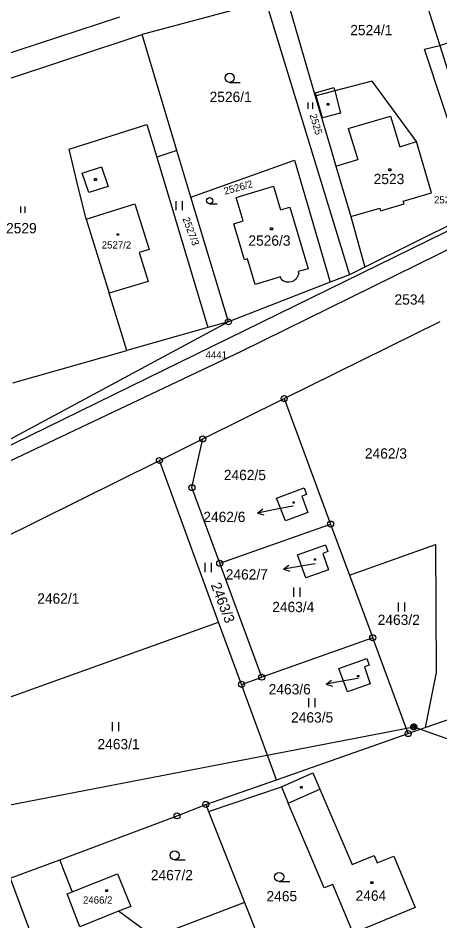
# Model space of a CAD drawing. Extents: x -468021 to -466942, y -1130484 to -1128584.
# Drawn here: x -467879.7 to -467810, y -1129830.2 to -1129681.1 of the extents above; entities that cross this region are included whole.
import ezdxf

# ---------------------------------------------------------------- set-up
doc = ezdxf.new("R2010")
doc.units = 0
doc.layers.add('DKM', color=7, linetype='Continuous')

msp = doc.modelspace()

# ---------------------------------------------------------------- linework, layer by layer
at = {"layer": 'DKM'}
for p, q in [((-467814.36, -1129671.87), (-467810.02, -1129685.66)), ((-467835.37, -1129677.48), (-467830.6, -1129694.02)), ((-467838.73, -1129678.38), (-467859.18, -1129683.85)), ((-467838.73, -1129678.38), (-467824.94, -1129723.51)), ((-467862.9, -1129680.96), (-467888.61, -1129689.4)), ((-467894.35, -1129695.47), (-467859.18, -1129683.85)), ((-467857.14, -1129690.66), (-467859.18, -1129683.85)), ((-467812.52, -1129686.25), (-467810.02, -1129685.66)), ((-467810.02, -1129685.66), (-467805.91, -1129684.3)), ((-467810.02, -1129685.66), (-467801.73, -1129712)), ((-467803.72, -1129712.98), (-467812.52, -1129686.25)), ((-467853.43, -1129703.02), (-467857.14, -1129690.66)), ((-467821.18, -1129691.55), (-467827.34, -1129693.17)), ((-467813.83, -1129701.51), (-467821.18, -1129691.55)), ((-467844.73, -1129691.74), (-467842.98, -1129691.74)), ((-467830.56, -1129693.49), (-467827.49, -1129692.6)), ((-467827.49, -1129692.6), (-467827.34, -1129693.17)), ((-467830.42, -1129693.97), (-467830.6, -1129694.02)), ((-467830.6, -1129694.02), (-467828.01, -1129702.73)), ((-467830.42, -1129693.97), (-467830.56, -1129693.49)), ((-467827.34, -1129693.17), (-467830.42, -1129693.97)), ((-467829.36, -1129697.62), (-467830.42, -1129693.97)), ((-467827.34, -1129693.17), (-467826.39, -1129696.83)), ((-467831.75, -1129696.11), (-467831.75, -1129695.06)), ((-467831.05, -1129695.06), (-467831.05, -1129696.11)), ((-467828.61, -1129695.23), (-467828.31, -1129695.23)), ((-467828.61, -1129695.53), (-467828.61, -1129695.23)), ((-467828.31, -1129695.53), (-467828.61, -1129695.53)), ((-467828.31, -1129695.23), (-467828.31, -1129695.53)), ((-467826.39, -1129696.83), (-467829.36, -1129697.62)), ((-467825.13, -1129699.37), (-467818.16, -1129697.35)), ((-467818.16, -1129697.35), (-467816.62, -1129702.37)), ((-467871.25, -1129702.79), (-467858.38, -1129698.7)), ((-467858.38, -1129698.7), (-467856.76, -1129704.09)), ((-467825.13, -1129699.37), (-467823.54, -1129704.48)), ((-467816.62, -1129702.37), (-467813.83, -1129701.51)), ((-467811.35, -1129709.98), (-467813.83, -1129701.51)), ((-467896.28, -1129759.16), (-467780.41, -1129702.4)), ((-467869.89, -1129708.32), (-467871.25, -1129702.79)), ((-467853.43, -1129703.02), (-467856.76, -1129704.09)), ((-467851.12, -1129710.71), (-467853.43, -1129703.02)), ((-467842.76, -1129736.13), (-467776.17, -1129703.37)), ((-467828.01, -1129702.73), (-467827.16, -1129705.59)), ((-467856.76, -1129704.09), (-467848.31, -1129732.25)), ((-467851.12, -1129710.71), (-467834.03, -1129704.6)), ((-467834.03, -1129704.6), (-467828.09, -1129724.74)), ((-467827.16, -1129705.59), (-467823.54, -1129704.48)), ((-467869.09, -1129706.76), (-467865.87, -1129705.7)), ((-467865.87, -1129705.7), (-467864.81, -1129708.92)), ((-467827.16, -1129705.59), (-467824.68, -1129713.91)), ((-467818.41, -1129706.03), (-467818.11, -1129706.03)), ((-467818.41, -1129706.33), (-467818.41, -1129706.03)), ((-467818.11, -1129706.33), (-467818.41, -1129706.33)), ((-467818.11, -1129706.03), (-467818.11, -1129706.33)), ((-467867.99, -1129709.95), (-467869.09, -1129706.76)), ((-467867.03, -1129707.64), (-467866.73, -1129707.64)), ((-467867.03, -1129707.94), (-467867.03, -1129707.64)), ((-467866.73, -1129707.94), (-467867.03, -1129707.94)), ((-467866.73, -1129707.64), (-467866.73, -1129707.94)), ((-467868.42, -1129714.33), (-467869.89, -1129708.32)), ((-467864.81, -1129708.92), (-467867.99, -1129709.95)), ((-467843.66, -1129710.75), (-467837.47, -1129708.91)), ((-467837.47, -1129708.91), (-467836.32, -1129712.79)), ((-467844.92, -1129731.29), (-467851.12, -1129710.71)), ((-467842.51, -1129714.62), (-467843.66, -1129710.75)), ((-467816.03, -1129711.36), (-467811.35, -1129709.98)), ((-467879.24, -1129713.31), (-467879.24, -1129712.26)), ((-467878.54, -1129712.26), (-467878.54, -1129713.31)), ((-467868.42, -1129714.33), (-467860.37, -1129711.79)), ((-467860.37, -1129711.79), (-467858.03, -1129719.32)), ((-467853.56, -1129712.87), (-467853.56, -1129711.37)), ((-467852.56, -1129711.37), (-467852.56, -1129712.87)), ((-467848.03, -1129711.81), (-467846.8, -1129711.81)), ((-467836.32, -1129712.79), (-467834.78, -1129712.33)), ((-467834.78, -1129712.33), (-467831.74, -1129722.51)), ((-467819.8, -1129712.94), (-467815.9, -1129711.79)), ((-467815.9, -1129711.79), (-467816.03, -1129711.36)), ((-467824.68, -1129713.91), (-467819.93, -1129712.51)), ((-467824.68, -1129713.91), (-467822.41, -1129722.26)), ((-467803.72, -1129712.98), (-467822.41, -1129722.26)), ((-467819.93, -1129712.51), (-467819.8, -1129712.94)), ((-467868.42, -1129714.33), (-467864.61, -1129726.57)), ((-467844.05, -1129715.08), (-467842.51, -1129714.62)), ((-467842.28, -1129721.05), (-467844.05, -1129715.08)), ((-467863.3, -1129716.75), (-467863.09, -1129716.75)), ((-467863.3, -1129716.96), (-467863.3, -1129716.75)), ((-467863.09, -1129716.96), (-467863.3, -1129716.96)), ((-467863.09, -1129716.75), (-467863.09, -1129716.96)), ((-467837.96, -1129715.78), (-467837.66, -1129715.78)), ((-467837.96, -1129716.08), (-467837.96, -1129715.78)), ((-467837.66, -1129716.08), (-467837.96, -1129716.08)), ((-467837.66, -1129715.78), (-467837.66, -1129716.08)), ((-467858.03, -1129719.32), (-467859.64, -1129719.82)), ((-467859.64, -1129719.82), (-467858.16, -1129724.62)), ((-467841.79, -1129720.9), (-467842.28, -1129721.05)), ((-467840.53, -1129725.15), (-467841.79, -1129720.9)), ((-467831.74, -1129722.51), (-467833.42, -1129723)), ((-467822.41, -1129722.26), (-467824.94, -1129723.51)), ((-467836.3, -1129723.88), (-467840.53, -1129725.15)), ((-467836.19, -1129724.24), (-467836.3, -1129723.88)), ((-467833.42, -1129723), (-467833.31, -1129723.38)), ((-467824.94, -1129723.51), (-467828.09, -1129724.74)), ((-467858.16, -1129724.62), (-467864.61, -1129726.57)), ((-467828.09, -1129724.74), (-467844.92, -1129731.29)), ((-467861.7, -1129736.03), (-467864.61, -1129726.57)), ((-467844.92, -1129731.29), (-467889.68, -1129755.39)), ((-467844.92, -1129731.29), (-467848.31, -1129732.25)), ((-467835.71, -1129743.97), (-467809.94, -1129731.21)), ((-467848.31, -1129732.25), (-467861.7, -1129736.03)), ((-467895.38, -1129761.08), (-467842.76, -1129736.13)), ((-467880.53, -1129741.34), (-467861.7, -1129736.03)), ((-467849.16, -1129750.63), (-467835.71, -1129743.97)), ((-467835.71, -1129743.97), (-467828.04, -1129764.68)), ((-467856.33, -1129754.19), (-467849.16, -1129750.63)), ((-467850.95, -1129758.66), (-467849.16, -1129750.63)), ((-467887.1, -1129769.42), (-467856.33, -1129754.19)), ((-467846.54, -1129780.88), (-467856.33, -1129754.19)), ((-467846.35, -1129771.16), (-467850.95, -1129758.66)), ((-467836.98, -1129760.42), (-467832.43, -1129758.69)), ((-467832.43, -1129758.69), (-467832.02, -1129759.78)), ((-467832.02, -1129759.78), (-467832.8, -1129760.08)), ((-467832.8, -1129760.08), (-467831.79, -1129762.76)), ((-467835.49, -1129764.16), (-467836.98, -1129760.42)), ((-467834.25, -1129761.03), (-467834.04, -1129761.03)), ((-467834.25, -1129761.24), (-467834.25, -1129761.03)), ((-467834.04, -1129761.24), (-467834.25, -1129761.24)), ((-467834.04, -1129761.03), (-467834.04, -1129761.24)), ((-467840.12, -1129762.87), (-467839.24, -1129762.19)), ((-467837.18, -1129762.3), (-467840.12, -1129762.87)), ((-467840.12, -1129762.87), (-467839.05, -1129763.17)), ((-467834.3, -1129761.74), (-467837.18, -1129762.3)), ((-467831.79, -1129762.76), (-467835.49, -1129764.16)), ((-467846.35, -1129771.16), (-467828.04, -1129764.68)), ((-467828.04, -1129764.68), (-467824.91, -1129773.13)), ((-467833.52, -1129769.75), (-467828.9, -1129768.13)), ((-467828.9, -1129768.13), (-467828.51, -1129769.24)), ((-467824.91, -1129773.13), (-467810.72, -1129768.04)), ((-467810.72, -1129768.04), (-467810.63, -1129789.2)), ((-467832.13, -1129773.55), (-467833.52, -1129769.75)), ((-467830.73, -1129770.44), (-467830.52, -1129770.44)), ((-467830.73, -1129770.65), (-467830.73, -1129770.44)), ((-467830.52, -1129770.65), (-467830.73, -1129770.65)), ((-467830.52, -1129770.44), (-467830.52, -1129770.65)), ((-467828.51, -1129769.24), (-467829.31, -1129769.52)), ((-467829.31, -1129769.52), (-467828.37, -1129772.24)), ((-467848.79, -1129772.61), (-467848.79, -1129771.11)), ((-467847.79, -1129771.11), (-467847.79, -1129772.61)), ((-467839.42, -1129789.97), (-467846.35, -1129771.16)), ((-467835.84, -1129772.15), (-467834.93, -1129771.49)), ((-467832.88, -1129771.65), (-467835.84, -1129772.15)), ((-467830.59, -1129771.27), (-467832.88, -1129771.65)), ((-467835.84, -1129772.15), (-467834.77, -1129772.47)), ((-467828.37, -1129772.24), (-467832.13, -1129773.55)), ((-467824.91, -1129773.13), (-467821.08, -1129783.46)), ((-467834.13, -1129776.68), (-467834.13, -1129775.18)), ((-467833.13, -1129775.18), (-467833.13, -1129776.68)), ((-467816.82, -1129779.14), (-467816.82, -1129777.64)), ((-467815.82, -1129777.64), (-467815.82, -1129779.14)), ((-467890.52, -1129796.64), (-467846.54, -1129780.88)), ((-467842.76, -1129791.15), (-467846.54, -1129780.88)), ((-467821.08, -1129783.46), (-467839.42, -1129789.97)), ((-467815.23, -1129799.28), (-467821.08, -1129783.46)), ((-467826.68, -1129788.54), (-467822.04, -1129786.91)), ((-467822.04, -1129786.91), (-467821.66, -1129788)), ((-467825.24, -1129792.36), (-467826.68, -1129788.54)), ((-467821.66, -1129788), (-467822.46, -1129788.28)), ((-467822.46, -1129788.28), (-467821.49, -1129791.04)), ((-467842.76, -1129791.15), (-467839.42, -1129789.97)), ((-467823.59, -1129789.68), (-467823.38, -1129789.68)), ((-467823.59, -1129789.89), (-467823.59, -1129789.68)), ((-467823.38, -1129789.89), (-467823.59, -1129789.89)), ((-467823.38, -1129789.68), (-467823.38, -1129789.89)), ((-467810.63, -1129789.2), (-467812.25, -1129797.46)), ((-467837, -1129806.9), (-467842.76, -1129791.15)), ((-467828.78, -1129791.11), (-467827.89, -1129790.44)), ((-467825.83, -1129790.59), (-467828.78, -1129791.11)), ((-467828.78, -1129791.11), (-467827.71, -1129791.43)), ((-467823.55, -1129790.19), (-467825.83, -1129790.59)), ((-467821.49, -1129791.04), (-467825.24, -1129792.36)), ((-467831.66, -1129794.92), (-467831.66, -1129793.42)), ((-467830.66, -1129793.42), (-467830.66, -1129794.92)), ((-467812.41, -1129798.29), (-467805, -1129795.7)), ((-467864.06, -1129798.88), (-467864.06, -1129797.38)), ((-467863.06, -1129797.38), (-467863.06, -1129798.88)), ((-467812.25, -1129797.46), (-467812.41, -1129798.29)), ((-467886.11, -1129812), (-467814.31, -1129798.17)), ((-467815.23, -1129799.28), (-467812.41, -1129798.29)), ((-467814.81, -1129798.07), (-467814.71, -1129797.87)), ((-467814.81, -1129798.27), (-467814.81, -1129798.07)), ((-467814.71, -1129798.47), (-467814.81, -1129798.27)), ((-467814.71, -1129797.87), (-467814.61, -1129797.77)), ((-467814.61, -1129798.57), (-467814.71, -1129798.47)), ((-467814.61, -1129797.77), (-467814.41, -1129797.67)), ((-467814.61, -1129797.97), (-467814.61, -1129798.37)), ((-467814.61, -1129798.37), (-467814.41, -1129798.47)), ((-467814.41, -1129798.67), (-467814.61, -1129798.57)), ((-467814.41, -1129797.67), (-467814.21, -1129797.67)), ((-467814.41, -1129798.47), (-467814.41, -1129797.87)), ((-467814.41, -1129797.87), (-467814.21, -1129797.87)), ((-467814.21, -1129798.67), (-467814.41, -1129798.67)), ((-467814.31, -1129798.17), (-467752.95, -1129819.79)), ((-467814.21, -1129797.67), (-467814.01, -1129797.77)), ((-467814.21, -1129797.87), (-467814.21, -1129798.47)), ((-467814.21, -1129798.47), (-467814.01, -1129798.37)), ((-467814.01, -1129798.57), (-467814.21, -1129798.67)), ((-467814.01, -1129797.77), (-467813.91, -1129797.87)), ((-467814.01, -1129798.37), (-467814.01, -1129797.97)), ((-467813.91, -1129798.47), (-467814.01, -1129798.57)), ((-467813.91, -1129797.87), (-467813.81, -1129798.07)), ((-467813.81, -1129798.27), (-467813.91, -1129798.47)), ((-467813.81, -1129798.07), (-467813.81, -1129798.27)), ((-467837, -1129806.9), (-467815.23, -1129799.28)), ((-467836.17, -1129808.06), (-467830.96, -1129805.79)), ((-467830.96, -1129805.79), (-467829.83, -1129808.48)), ((-467848.66, -1129810.98), (-467837, -1129806.9)), ((-467848.19, -1129812.16), (-467836.17, -1129808.06)), ((-467836.17, -1129808.06), (-467835.07, -1129810.79)), ((-467835.07, -1129810.79), (-467829.83, -1129808.48)), ((-467833.04, -1129808.02), (-467832.74, -1129808.02)), ((-467833.04, -1129808.32), (-467833.04, -1129808.02)), ((-467832.74, -1129808.32), (-467833.04, -1129808.32)), ((-467832.74, -1129808.02), (-467832.74, -1129808.32)), ((-467829.83, -1129808.48), (-467824.5, -1129820.91)), ((-467829.09, -1129824.76), (-467835.07, -1129810.79)), ((-467853.41, -1129812.87), (-467848.66, -1129810.98)), ((-467848.66, -1129810.98), (-467848.19, -1129812.16)), ((-467848.19, -1129812.16), (-467842.25, -1129827.18)), ((-467872.8, -1129820.11), (-467853.41, -1129812.87)), ((-467824.5, -1129820.91), (-467820.83, -1129819.39)), ((-467820.83, -1129819.39), (-467820.34, -1129820.6)), ((-467820.34, -1129820.6), (-467817.6, -1129819.5)), ((-467817.6, -1129819.5), (-467814.05, -1129828.01)), ((-467880.96, -1129823.16), (-467872.8, -1129820.11)), ((-467872.8, -1129820.11), (-467872.32, -1129821.37)), ((-467853.82, -1129820.12), (-467852.07, -1129820.12)), ((-467872.32, -1129821.37), (-467870.76, -1129825.44)), ((-467870.76, -1129825.44), (-467863.22, -1129822.42)), ((-467863.22, -1129822.42), (-467861.07, -1129827.84)), ((-467880.96, -1129823.16), (-467874.82, -1129839.61)), ((-467836.54, -1129823.71), (-467834.79, -1129823.71)), ((-467827.69, -1129824.18), (-467829.09, -1129824.76)), ((-467824.33, -1129832.26), (-467827.69, -1129824.18)), ((-467821.39, -1129823.75), (-467821.09, -1129823.75)), ((-467821.39, -1129824.05), (-467821.39, -1129823.75)), ((-467821.09, -1129824.05), (-467821.39, -1129824.05)), ((-467821.09, -1129823.75), (-467821.09, -1129824.05)), ((-467871.58, -1129825.77), (-467870.76, -1129825.44)), ((-467869.46, -1129831.18), (-467871.58, -1129825.77)), ((-467865.18, -1129825.06), (-467864.88, -1129825.06)), ((-467865.18, -1129825.36), (-467865.18, -1129825.06)), ((-467864.88, -1129825.36), (-467865.18, -1129825.36)), ((-467864.88, -1129825.06), (-467864.88, -1129825.36)), ((-467842.25, -1129827.18), (-467857.27, -1129832.91)), ((-467842.25, -1129827.18), (-467836.31, -1129842.2)), ((-467863.06, -1129828.63), (-467869.46, -1129831.18)), ((-467861.07, -1129827.84), (-467863.06, -1129828.63)), ((-467857.27, -1129832.91), (-467863.06, -1129828.63)), ((-467814.05, -1129828.01), (-467824.33, -1129832.26))]:
    msp.add_line(p, q, dxfattribs=at)
for centre, radius in [((-467844.73, -1129690.99), 0.75), ((-467848.03, -1129711.29), 0.525), ((-467844.92, -1129731.29), 0.5), ((-467844.92, -1129731.29), 0.01), ((-467835.71, -1129743.97), 0.5), ((-467835.71, -1129743.97), 0.01), ((-467849.16, -1129750.63), 0.5), ((-467849.16, -1129750.63), 0.01), ((-467856.33, -1129754.19), 0.5), ((-467856.33, -1129754.19), 0.01), ((-467850.95, -1129758.66), 0.5), ((-467850.95, -1129758.66), 0.01), ((-467828.04, -1129764.68), 0.5), ((-467828.04, -1129764.68), 0.01), ((-467846.35, -1129771.16), 0.5), ((-467846.35, -1129771.16), 0.01), ((-467821.08, -1129783.46), 0.5), ((-467821.08, -1129783.46), 0.01), ((-467839.42, -1129789.97), 0.5), ((-467839.42, -1129789.97), 0.01), ((-467842.76, -1129791.15), 0.5), ((-467842.76, -1129791.15), 0.01), ((-467815.23, -1129799.28), 0.5), ((-467815.23, -1129799.28), 0.01), ((-467848.66, -1129810.98), 0.5), ((-467853.41, -1129812.87), 0.5), ((-467848.66, -1129810.98), 0.01), ((-467853.41, -1129812.87), 0.01), ((-467853.82, -1129819.37), 0.75), ((-467836.54, -1129822.96), 0.75)]:
    msp.add_circle(centre, radius, dxfattribs=at)
msp.add_arc((-467835, -1129722.98), 1.73, 226.5774, 346.675, dxfattribs=at)

# ---------------------------------------------------------------- texts
for s, height, p in [('2524/1', 1.7, (-467824.79, -1129683.96)), ('2526/1', 1.7, (-467848.03, -1129694.99)), ('2523', 1.7, (-467820.93, -1129708.55)), ('2524/6', 1.19, (-467810.96, -1129711.74)), ('2529', 1.7, (-467881.65, -1129716.67)), ('2526/3', 1.7, (-467841.62, -1129718.72)), ('2527/2', 1.19, (-467865.85, -1129719.18)), ('2534', 1.7, (-467817.48, -1129728.45)), ('4441', 1.19, (-467848.7, -1129737.33)), ('2462/3', 1.7, (-467822.38, -1129753.87)), ('2462/5', 1.7, (-467845.68, -1129757.43)), ('2462/6', 0.1, (-467834.3, -1129761.74)), ('2462/6', 1.7, (-467849.07, -1129764.35)), ('2462/7', 1.7, (-467845.36, -1129773.85)), ('2462/7', 0.1, (-467830.59, -1129771.27)), ('2462/1', 1.7, (-467876.5, -1129777.82)), ('2463/4', 1.7, (-467837.69, -1129779.23)), ('2463/2', 1.7, (-467820.26, -1129781.34)), ('2463/6', 1.7, (-467838.27, -1129792.81)), ('2463/6', 0.1, (-467823.55, -1129790.19)), ('2463/5', 1.7, (-467834.57, -1129797.46)), ('2463/1', 1.7, (-467866.55, -1129801.87)), ('2467/2', 1.7, (-467857.74, -1129823.5)), ('2465', 1.7, (-467838.63, -1129826.98)), ('2464', 1.7, (-467823.92, -1129826.89)), ('2466/2', 1.19, (-467868.95, -1129827.36))]:
    msp.add_text(s, height=height, dxfattribs=at).set_placement(p)
for s, height, rotation, p in [('2525', 1.19, 286.8349, (-467831.53, -1129697.14)), ('2526/2', 1.19, 15.2893, (-467845.5, -1129710.31)), ('2527/3', 1.19, 290.6436, (-467852.53, -1129714.27)), ('2463/3', 1.7, 290.799, (-467847.86, -1129774.72))]:
    msp.add_text(s, height=height, rotation=rotation, dxfattribs=at).set_placement(p)

doc.saveas('drawing.dxf')
